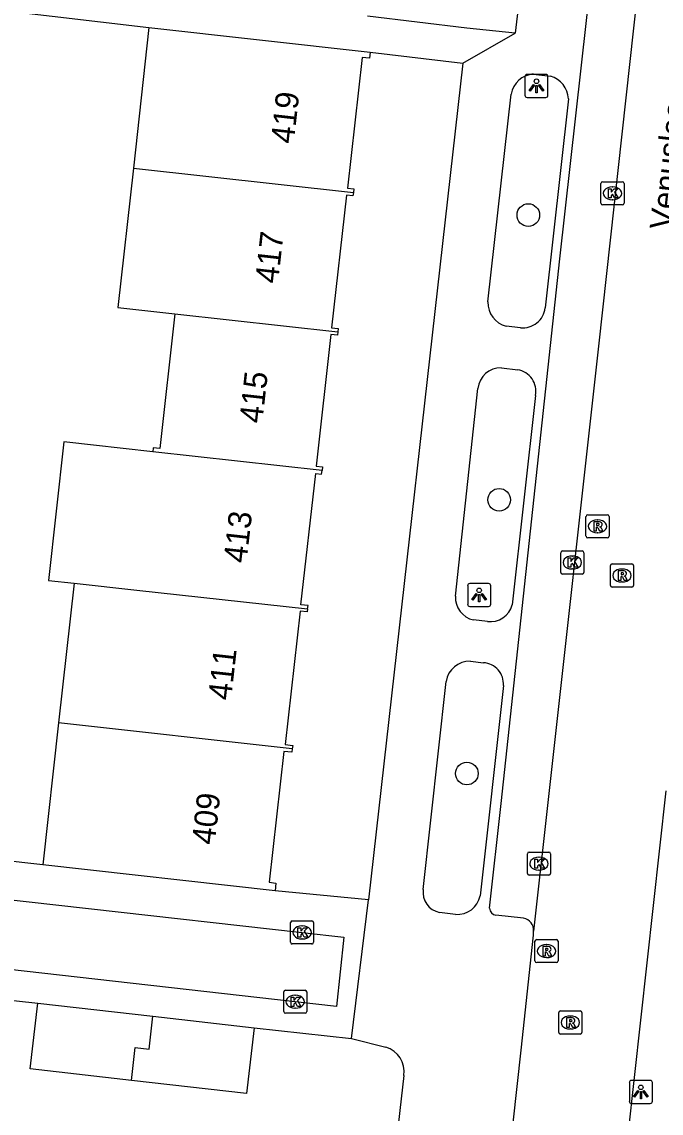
# Model space of a CAD drawing. Extents: x 161928 to 163055, y 386475 to 387428.
# Drawn here: x 162058.37 to 162086.04, y 386860.17 to 386907.42 of the extents above; entities that cross this region are included whole.
import ezdxf

# ---------------------------------------------------------------- set-up
doc = ezdxf.new("R2010")
doc.units = 0
for name, color, linetype in [('IMGEO_Boom', 7, 'Continuous'), ('IMGEO_Kolk', 7, 'Continuous'), ('IMGEO_Lichtpunt', 7, 'Continuous'), ('IMGEO_Openbare_ruimte_label', 7, 'Continuous'), ('IMGEO_Pand', 7, 'Continuous'), ('IMGEO_Pand_nummerreeks', 7, 'Continuous'), ('IMGEO_Rijbaan_lokaal_open', 7, 'Continuous'), ('IMGEO_Rioolput', 7, 'Continuous'), ('IMGEO_Voetpad_open', 7, 'Continuous')]:
    doc.layers.add(name, color=color, linetype=linetype)

msp = doc.modelspace()

# ---------------------------------------------------------------- linework, layer by layer
at = {"layer": 'IMGEO_Boom'}
for centre in [(162080.288, 386899.055), (162079.03, 386886.729), (162077.631, 386874.872)]:
    msp.add_circle(centre, 0.489, dxfattribs=at)
at = {"layer": 'IMGEO_Kolk'}
for p, q in [((162083.43, 386899.569), (162083.43, 386900.421)), ((162083.505, 386900.495), (162084.357, 386900.495)), ((162084.431, 386900.421), (162084.431, 386899.569)), ((162083.918, 386900.275), (162083.943, 386900.275)), ((162084.357, 386899.495), (162083.505, 386899.495)), ((162083.941, 386899.715), (162083.916, 386899.715)), ((162081.691, 386883.585), (162081.691, 386884.437)), ((162081.766, 386884.511), (162082.618, 386884.511)), ((162082.692, 386884.437), (162082.692, 386883.585)), ((162082.179, 386884.291), (162082.204, 386884.291)), ((162082.618, 386883.511), (162081.766, 386883.511)), ((162082.202, 386883.731), (162082.177, 386883.731)), ((162080.248, 386870.548), (162080.248, 386871.4)), ((162080.323, 386871.474), (162081.175, 386871.474)), ((162080.736, 386871.254), (162080.761, 386871.254)), ((162081.249, 386871.4), (162081.249, 386870.548)), ((162080.759, 386870.694), (162080.734, 386870.694)), ((162081.175, 386870.474), (162080.323, 386870.474)), ((162069.996, 386867.568), (162069.996, 386868.42)), ((162070.071, 386868.494), (162070.923, 386868.494)), ((162070.484, 386868.274), (162070.509, 386868.274)), ((162070.997, 386868.42), (162070.997, 386867.568)), ((162070.923, 386867.494), (162070.071, 386867.494)), ((162070.507, 386867.714), (162070.482, 386867.714)), ((162069.7, 386864.569), (162069.7, 386865.421)), ((162069.775, 386865.495), (162070.627, 386865.495)), ((162070.701, 386865.421), (162070.701, 386864.569)), ((162070.188, 386865.275), (162070.213, 386865.275)), ((162070.627, 386864.495), (162069.775, 386864.495)), ((162070.211, 386864.715), (162070.186, 386864.715))]:
    msp.add_line(p, q, dxfattribs=at)
for points in [[(162083.43, 386899.569), (162083.43, 386900.421)], [(162083.505, 386900.495), (162084.357, 386900.495)], [(162084.431, 386900.421), (162084.431, 386899.569)], [(162083.751, 386900.195), (162083.874, 386900.195), (162083.874, 386900.044), (162084.004, 386900.195), (162084.168, 386900.195), (162084.022, 386900.044), (162084.175, 386899.795), (162084.023, 386899.795), (162083.938, 386899.959), (162083.874, 386899.892), (162083.874, 386899.795), (162083.751, 386899.795), (162083.751, 386900.195)], [(162084.357, 386899.495), (162083.505, 386899.495)], [(162081.691, 386883.585), (162081.691, 386884.437)], [(162081.766, 386884.511), (162082.618, 386884.511)], [(162082.692, 386884.437), (162082.692, 386883.585)], [(162082.012, 386884.211), (162082.135, 386884.211), (162082.135, 386884.06), (162082.265, 386884.211), (162082.429, 386884.211), (162082.283, 386884.06), (162082.436, 386883.811), (162082.284, 386883.811), (162082.199, 386883.975), (162082.135, 386883.908), (162082.135, 386883.811), (162082.012, 386883.811), (162082.012, 386884.211)], [(162082.618, 386883.511), (162081.766, 386883.511)], [(162080.248, 386870.548), (162080.248, 386871.4)], [(162080.323, 386871.474), (162081.175, 386871.474)], [(162080.569, 386871.174), (162080.692, 386871.174), (162080.692, 386871.023), (162080.822, 386871.174), (162080.986, 386871.174), (162080.84, 386871.023), (162080.993, 386870.774), (162080.841, 386870.774), (162080.756, 386870.938), (162080.692, 386870.871), (162080.692, 386870.774), (162080.569, 386870.774), (162080.569, 386871.174)], [(162081.249, 386871.4), (162081.249, 386870.548)], [(162081.175, 386870.474), (162080.323, 386870.474)], [(162069.996, 386867.568), (162069.996, 386868.42)], [(162070.071, 386868.494), (162070.923, 386868.494)], [(162070.997, 386868.42), (162070.997, 386867.568)], [(162070.317, 386868.194), (162070.44, 386868.194), (162070.44, 386868.043), (162070.57, 386868.194), (162070.734, 386868.194), (162070.588, 386868.043), (162070.741, 386867.794), (162070.589, 386867.794), (162070.504, 386867.958), (162070.44, 386867.891), (162070.44, 386867.794), (162070.317, 386867.794), (162070.317, 386868.194)], [(162070.923, 386867.494), (162070.071, 386867.494)], [(162069.7, 386864.569), (162069.7, 386865.421)], [(162069.775, 386865.495), (162070.627, 386865.495)], [(162070.701, 386865.421), (162070.701, 386864.569)], [(162070.021, 386865.195), (162070.144, 386865.195), (162070.144, 386865.044), (162070.274, 386865.195), (162070.438, 386865.195), (162070.292, 386865.044), (162070.445, 386864.795), (162070.293, 386864.795), (162070.208, 386864.959), (162070.144, 386864.892), (162070.144, 386864.795), (162070.021, 386864.795), (162070.021, 386865.195)], [(162070.627, 386864.495), (162069.775, 386864.495)]]:
    msp.add_lwpolyline(points, dxfattribs=at)
for centre, start, end in [((162083.507, 386900.419), 91.552, 178.448), ((162083.507, 386900.419), 91.552, 178.448), ((162084.355, 386900.419), 1.552, 88.448), ((162084.355, 386900.419), 1.552, 88.448), ((162083.507, 386899.571), 181.552, 268.448), ((162083.507, 386899.571), 181.552, 268.448), ((162084.355, 386899.571), 271.552, 358.448), ((162084.355, 386899.571), 271.552, 358.448), ((162081.768, 386884.435), 91.552, 178.448), ((162081.768, 386884.435), 91.552, 178.448), ((162082.616, 386884.435), 1.552, 88.448), ((162082.616, 386884.435), 1.552, 88.448), ((162081.768, 386883.587), 181.552, 268.448), ((162081.768, 386883.587), 181.552, 268.448), ((162082.616, 386883.587), 271.552, 358.448), ((162082.616, 386883.587), 271.552, 358.448), ((162080.325, 386871.398), 91.552, 178.448), ((162080.325, 386871.398), 91.552, 178.448), ((162081.173, 386871.398), 1.552, 88.448), ((162081.173, 386871.398), 1.552, 88.448), ((162080.325, 386870.55), 181.552, 268.448), ((162080.325, 386870.55), 181.552, 268.448), ((162081.173, 386870.55), 271.552, 358.448), ((162081.173, 386870.55), 271.552, 358.448), ((162070.073, 386868.418), 91.552, 178.448), ((162070.073, 386868.418), 91.552, 178.448), ((162070.921, 386868.418), 1.552, 88.448), ((162070.921, 386868.418), 1.552, 88.448), ((162070.073, 386867.57), 181.552, 268.448), ((162070.073, 386867.57), 181.552, 268.448), ((162070.921, 386867.57), 271.552, 358.448), ((162070.921, 386867.57), 271.552, 358.448), ((162069.777, 386865.419), 91.552, 178.448), ((162069.777, 386865.419), 91.552, 178.448), ((162070.625, 386865.419), 1.552, 88.448), ((162070.625, 386865.419), 1.552, 88.448), ((162069.777, 386864.571), 181.552, 268.448), ((162069.777, 386864.571), 181.552, 268.448), ((162070.625, 386864.571), 271.552, 358.448), ((162070.625, 386864.571), 271.552, 358.448)]:
    msp.add_arc(centre, 0.0765, start, end, dxfattribs=at)
for centre, major_axis, ratio, start_param, end_param in [((162083.917, 386899.995), (-0.387, 0.002), 0.722429, 4.712389, 7.853982), ((162083.942, 386899.995), (-0.39, 0.002), 0.717154, 1.570796, 4.712389), ((162082.178, 386884.011), (-0.387, 0.002), 0.722429, 4.712389, 7.853982), ((162082.203, 386884.011), (-0.39, 0.002), 0.717154, 1.570796, 4.712389), ((162080.735, 386870.974), (-0.387, 0.002), 0.722429, 4.712389, 7.853982), ((162080.76, 386870.974), (-0.39, 0.002), 0.717154, 1.570796, 4.712389), ((162070.483, 386867.994), (-0.387, 0.002), 0.722429, 4.712389, 7.853982), ((162070.508, 386867.994), (-0.39, 0.002), 0.717154, 1.570796, 4.712389), ((162070.187, 386864.995), (-0.387, 0.002), 0.722429, 4.712389, 7.853982), ((162070.212, 386864.995), (-0.39, 0.002), 0.717154, 1.570796, 4.712389)]:
    msp.add_ellipse(centre, major_axis=major_axis, ratio=ratio, start_param=start_param, end_param=end_param, dxfattribs=at)
at = {"layer": 'IMGEO_Lichtpunt'}
for p, q in [((162081.045, 386905.144), (162080.237, 386905.144)), ((162081.045, 386905.144), (162080.237, 386905.144)), ((162080.143, 386905.049), (162080.143, 386904.242)), ((162080.143, 386905.049), (162080.143, 386904.242)), ((162081.139, 386904.242), (162081.139, 386905.049)), ((162081.139, 386904.242), (162081.139, 386905.049)), ((162080.237, 386904.148), (162081.045, 386904.148)), ((162080.237, 386904.148), (162081.045, 386904.148)), ((162077.663, 386883.008), (162077.663, 386882.201)), ((162077.663, 386883.008), (162077.663, 386882.201)), ((162078.565, 386883.103), (162077.757, 386883.103)), ((162078.565, 386883.103), (162077.757, 386883.103)), ((162078.659, 386882.201), (162078.659, 386883.008)), ((162078.659, 386882.201), (162078.659, 386883.008)), ((162077.757, 386882.107), (162078.565, 386882.107)), ((162077.757, 386882.107), (162078.565, 386882.107)), ((162084.66, 386861.491), (162084.66, 386860.684)), ((162084.66, 386861.491), (162084.66, 386860.684)), ((162085.562, 386861.586), (162084.754, 386861.586)), ((162085.562, 386861.586), (162084.754, 386861.586)), ((162085.656, 386860.684), (162085.656, 386861.491)), ((162085.656, 386860.684), (162085.656, 386861.491)), ((162084.754, 386860.59), (162085.562, 386860.59)), ((162084.754, 386860.59), (162085.562, 386860.59))]:
    msp.add_line(p, q, dxfattribs=at)
for points in [[(162080.517, 386904.713), (162080.556, 386904.685), (162080.368, 386904.423), (162080.33, 386904.45), (162080.517, 386904.713)], [(162080.619, 386904.665), (162080.666, 386904.665), (162080.666, 386904.343), (162080.619, 386904.343), (162080.619, 386904.665)], [(162080.729, 386904.685), (162080.767, 386904.712), (162080.954, 386904.45), (162080.915, 386904.422), (162080.729, 386904.685)], [(162078.037, 386882.672), (162078.076, 386882.644), (162077.888, 386882.382), (162077.85, 386882.409), (162078.037, 386882.672)], [(162078.139, 386882.624), (162078.186, 386882.624), (162078.186, 386882.302), (162078.139, 386882.302), (162078.139, 386882.624)], [(162078.249, 386882.644), (162078.287, 386882.671), (162078.474, 386882.409), (162078.435, 386882.381), (162078.249, 386882.644)], [(162085.034, 386861.155), (162085.073, 386861.127), (162084.885, 386860.865), (162084.847, 386860.892), (162085.034, 386861.155)], [(162085.246, 386861.127), (162085.284, 386861.154), (162085.471, 386860.892), (162085.432, 386860.864), (162085.246, 386861.127)], [(162085.136, 386861.107), (162085.183, 386861.107), (162085.183, 386860.785), (162085.136, 386860.785), (162085.136, 386861.107)]]:
    msp.add_lwpolyline(points, dxfattribs=at)
for centre in [(162080.642, 386904.847), (162078.162, 386882.806), (162085.159, 386861.289)]:
    msp.add_circle(centre, 0.0994, dxfattribs=at)
for centre, start, end in [((162080.237, 386905.049), 90, 180), ((162080.237, 386905.049), 90, 180), ((162081.045, 386905.049), 0, 90), ((162081.045, 386905.049), 0, 90), ((162080.237, 386904.242), 180, 270), ((162080.237, 386904.242), 180, 270), ((162081.045, 386904.242), 270, 0), ((162081.045, 386904.242), 270, 360), ((162077.757, 386883.008), 90, 180), ((162077.757, 386883.008), 90, 180), ((162078.565, 386883.008), 0, 90), ((162078.565, 386883.008), 0, 90), ((162077.757, 386882.201), 180, 270), ((162077.757, 386882.201), 180, 270), ((162078.565, 386882.201), 270, 0), ((162078.565, 386882.201), 270, 360), ((162084.754, 386861.491), 90, 180), ((162084.754, 386861.491), 90, 180), ((162085.562, 386861.491), 0, 90), ((162085.562, 386861.491), 0, 90), ((162084.754, 386860.684), 180, 270), ((162084.754, 386860.684), 180, 270), ((162085.562, 386860.684), 270, 0), ((162085.562, 386860.684), 270, 360)]:
    msp.add_arc(centre, 0.0946, start, end, dxfattribs=at)
at = {"layer": 'IMGEO_Pand'}
for points in [[(162063.867, 386907.179), (162063.194, 386901.092)], [(162063.867, 386907.179), (162073.446, 386906.104)], [(162073.446, 386906.104), (162073.417, 386905.844), (162073.091, 386905.88), (162072.457, 386900.224), (162072.734, 386900.193), (162072.717, 386900.038)], [(162063.194, 386901.092), (162062.525, 386895.048), (162064.995, 386894.775)], [(162063.194, 386901.092), (162072.717, 386900.038)], [(162072.717, 386900.038), (162072.699, 386899.881), (162072.416, 386899.913), (162071.773, 386894.172), (162072.057, 386894.14), (162072.041, 386893.995)], [(162064.995, 386894.775), (162064.341, 386888.944), (162064.055, 386888.976), (162064.036, 386888.809)], [(162064.995, 386894.775), (162072.041, 386893.995)], [(162072.041, 386893.995), (162072.024, 386893.848), (162071.746, 386893.879), (162071.107, 386888.184), (162071.376, 386888.154), (162071.359, 386887.998)], [(162064.036, 386888.809), (162060.19, 386889.235), (162059.525, 386883.232), (162060.631, 386883.11)], [(162071.359, 386887.998), (162064.036, 386888.809)], [(162070.738, 386882.008), (162070.753, 386882.146), (162070.449, 386882.18), (162071.087, 386887.87), (162071.341, 386887.841), (162071.359, 386887.998)], [(162060.631, 386883.11), (162059.96, 386877.064)], [(162060.631, 386883.11), (162063.351, 386882.812), (162070.738, 386882.008)], [(162070.738, 386882.008), (162070.722, 386881.87), (162070.418, 386881.904), (162069.77, 386876.13), (162070.09, 386876.094), (162070.073, 386875.945)], [(162059.96, 386877.064), (162059.278, 386870.918)], [(162070.073, 386875.945), (162059.96, 386877.064)], [(162070.073, 386875.945), (162070.056, 386875.796), (162069.707, 386875.835), (162069.071, 386870.166), (162069.363, 386870.134), (162069.325, 386869.792)], [(162069.325, 386869.792), (162059.278, 386870.918)], [(162063.113, 386861.587), (162058.73, 386862.086), (162059.054, 386864.932)], [(162059.054, 386864.932), (162064.034, 386864.365)], [(162063.113, 386861.587), (162063.275, 386863.01), (162063.872, 386862.942), (162064.034, 386864.365)], [(162064.034, 386864.365), (162068.418, 386863.866)], [(162068.418, 386863.866), (162068.094, 386861.02), (162063.113, 386861.587)]]:
    msp.add_lwpolyline(points, dxfattribs=at)
at = {"layer": 'IMGEO_Rijbaan_lokaal_open'}
for points in [[(162087.202, 386928.662), (162083.328, 386893.374), (162081.119, 386873.495), (162080.519, 386868.055)], [(162084.603, 386859.23), (162086.247, 386874.125)], [(162050.693, 386870.214), (162051.991, 386870.069), (162070.497, 386867.994), (162072.306, 386867.789), (162071.98, 386864.795), (162070.201, 386864.995), (162051.445, 386867.107), (162040.29, 386868.47)], [(162079.639, 386859.749), (162079.983, 386862.893), (162080.511, 386867.872), (162080.519, 386868.055)]]:
    msp.add_lwpolyline(points, dxfattribs=at)
at = {"layer": 'IMGEO_Rioolput'}
for p, q in [((162082.784, 386885.151), (162082.784, 386886.003)), ((162082.859, 386886.077), (162083.711, 386886.077)), ((162083.272, 386885.857), (162083.297, 386885.857)), ((162083.785, 386886.003), (162083.785, 386885.151)), ((162083.295, 386885.297), (162083.27, 386885.297)), ((162083.711, 386885.077), (162082.859, 386885.077)), ((162083.842, 386883.023), (162083.842, 386883.875)), ((162083.917, 386883.949), (162084.769, 386883.949)), ((162084.843, 386883.875), (162084.843, 386883.023)), ((162084.33, 386883.729), (162084.355, 386883.729)), ((162084.769, 386882.949), (162083.917, 386882.949)), ((162084.353, 386883.169), (162084.328, 386883.169)), ((162080.575, 386866.761), (162080.575, 386867.613)), ((162080.65, 386867.687), (162081.502, 386867.687)), ((162081.063, 386867.467), (162081.088, 386867.467)), ((162081.576, 386867.613), (162081.576, 386866.761)), ((162081.086, 386866.907), (162081.061, 386866.907)), ((162081.502, 386866.687), (162080.65, 386866.687)), ((162081.606, 386863.669), (162081.606, 386864.521)), ((162081.681, 386864.595), (162082.533, 386864.595)), ((162082.607, 386864.521), (162082.607, 386863.669)), ((162082.094, 386864.375), (162082.119, 386864.375)), ((162082.533, 386863.595), (162081.681, 386863.595)), ((162082.117, 386863.815), (162082.092, 386863.815))]:
    msp.add_line(p, q, dxfattribs=at)
for points in [[(162082.784, 386885.151), (162082.784, 386886.003)], [(162082.859, 386886.077), (162083.711, 386886.077)], [(162083.373, 386885.775), (162083.121, 386885.777), (162083.121, 386885.377)], [(162083.785, 386886.003), (162083.785, 386885.151)], [(162083.121, 386885.377), (162083.245, 386885.377), (162083.245, 386885.539), (162083.256, 386885.539)], [(162083.299, 386885.696), (162083.245, 386885.696), (162083.245, 386885.615)], [(162083.245, 386885.615), (162083.297, 386885.615)], [(162083.303, 386885.51), (162083.374, 386885.377), (162083.514, 386885.377), (162083.449, 386885.503)], [(162083.711, 386885.077), (162082.859, 386885.077)], [(162083.842, 386883.023), (162083.842, 386883.875)], [(162083.917, 386883.949), (162084.769, 386883.949)], [(162084.843, 386883.875), (162084.843, 386883.023)], [(162084.431, 386883.647), (162084.179, 386883.649), (162084.179, 386883.249)], [(162084.179, 386883.249), (162084.303, 386883.249), (162084.303, 386883.411), (162084.314, 386883.411)], [(162084.357, 386883.568), (162084.303, 386883.568), (162084.303, 386883.487)], [(162084.303, 386883.487), (162084.355, 386883.487)], [(162084.361, 386883.382), (162084.432, 386883.249), (162084.572, 386883.249), (162084.507, 386883.375)], [(162084.769, 386882.949), (162083.917, 386882.949)], [(162080.575, 386866.761), (162080.575, 386867.613)], [(162080.65, 386867.687), (162081.502, 386867.687)], [(162081.164, 386867.385), (162080.912, 386867.387), (162080.912, 386866.987)], [(162081.09, 386867.306), (162081.036, 386867.306), (162081.036, 386867.225)], [(162081.576, 386867.613), (162081.576, 386866.761)], [(162080.912, 386866.987), (162081.036, 386866.987), (162081.036, 386867.149), (162081.047, 386867.149)], [(162081.036, 386867.225), (162081.088, 386867.225)], [(162081.094, 386867.12), (162081.165, 386866.987), (162081.305, 386866.987), (162081.24, 386867.113)], [(162081.502, 386866.687), (162080.65, 386866.687)], [(162081.606, 386863.669), (162081.606, 386864.521)], [(162081.681, 386864.595), (162082.533, 386864.595)], [(162082.607, 386864.521), (162082.607, 386863.669)], [(162082.195, 386864.293), (162081.943, 386864.295), (162081.943, 386863.895)], [(162081.943, 386863.895), (162082.067, 386863.895), (162082.067, 386864.057), (162082.078, 386864.057)], [(162082.121, 386864.214), (162082.067, 386864.214), (162082.067, 386864.133)], [(162082.067, 386864.133), (162082.119, 386864.133)], [(162082.125, 386864.028), (162082.196, 386863.895), (162082.336, 386863.895), (162082.271, 386864.021)], [(162082.533, 386863.595), (162081.681, 386863.595)]]:
    msp.add_lwpolyline(points, dxfattribs=at)
for centre, radius, start, end in [((162082.861, 386886.001), 0.0765, 91.552, 178.448), ((162082.861, 386886.001), 0.0765, 91.552, 178.448), ((162083.372, 386885.665), 0.109, 350.3612, 89.416), ((162083.709, 386886.001), 0.0765, 1.552, 88.448), ((162083.709, 386886.001), 0.0765, 1.552, 88.448), ((162083.255, 386885.486), 0.0533, 26.0293, 88.6989), ((162083.281, 386885.804), 0.19, 274.7715, 282.9687), ((162083.305, 386885.6), 0.0964, 77.0061, 93.1865), ((162083.319, 386885.657), 0.0378, 276.6634, 79.6772), ((162083.37, 386885.665), 0.112, 277.5842, 350.9817), ((162083.354, 386885.45), 0.108, 29.5134, 73.7905), ((162082.861, 386885.153), 0.0765, 181.552, 268.448), ((162082.861, 386885.153), 0.0765, 181.552, 268.448), ((162083.709, 386885.153), 0.0765, 271.552, 358.448), ((162083.709, 386885.153), 0.0765, 271.552, 358.448), ((162083.919, 386883.873), 0.0765, 91.552, 178.448), ((162083.919, 386883.873), 0.0765, 91.552, 178.448), ((162084.767, 386883.873), 0.0765, 1.552, 88.448), ((162084.767, 386883.873), 0.0765, 1.552, 88.448), ((162084.313, 386883.358), 0.0533, 26.0293, 88.6989), ((162084.339, 386883.676), 0.19, 274.7715, 282.9687), ((162084.363, 386883.472), 0.0964, 77.0061, 93.1865), ((162084.377, 386883.529), 0.0378, 276.6634, 79.6772), ((162084.43, 386883.537), 0.109, 350.3612, 89.416), ((162084.428, 386883.537), 0.112, 277.5842, 350.9817), ((162084.412, 386883.322), 0.108, 29.5134, 73.7905), ((162083.919, 386883.025), 0.0765, 181.552, 268.448), ((162083.919, 386883.025), 0.0765, 181.552, 268.448), ((162084.767, 386883.025), 0.0765, 271.552, 358.448), ((162084.767, 386883.025), 0.0765, 271.552, 358.448), ((162080.652, 386867.611), 0.0765, 91.552, 178.448), ((162080.652, 386867.611), 0.0765, 91.552, 178.448), ((162081.096, 386867.21), 0.0964, 77.0061, 93.1865), ((162081.11, 386867.267), 0.0378, 276.6634, 79.6772), ((162081.163, 386867.275), 0.109, 350.3612, 89.416), ((162081.5, 386867.611), 0.0765, 1.552, 88.448), ((162081.5, 386867.611), 0.0765, 1.552, 88.448), ((162081.046, 386867.096), 0.0533, 26.0293, 88.6989), ((162081.072, 386867.414), 0.19, 274.7715, 282.9687), ((162081.161, 386867.275), 0.112, 277.5842, 350.9817), ((162081.145, 386867.06), 0.108, 29.5134, 73.7905), ((162080.652, 386866.763), 0.0765, 181.552, 268.448), ((162080.652, 386866.763), 0.0765, 181.552, 268.448), ((162081.5, 386866.763), 0.0765, 271.552, 358.448), ((162081.5, 386866.763), 0.0765, 271.552, 358.448), ((162081.683, 386864.519), 0.0765, 91.552, 178.448), ((162081.683, 386864.519), 0.0765, 91.552, 178.448), ((162082.531, 386864.519), 0.0765, 1.552, 88.448), ((162082.531, 386864.519), 0.0765, 1.552, 88.448), ((162082.077, 386864.004), 0.0533, 26.0293, 88.6989), ((162082.103, 386864.322), 0.19, 274.7715, 282.9687), ((162082.127, 386864.118), 0.0964, 77.0061, 93.1865), ((162082.141, 386864.175), 0.0378, 276.6634, 79.6772), ((162082.194, 386864.183), 0.109, 350.3612, 89.416), ((162082.192, 386864.183), 0.112, 277.5842, 350.9817), ((162082.176, 386863.968), 0.108, 29.5134, 73.7905), ((162081.683, 386863.671), 0.0765, 181.552, 268.448), ((162081.683, 386863.671), 0.0765, 181.552, 268.448), ((162082.531, 386863.671), 0.0765, 271.552, 358.448), ((162082.531, 386863.671), 0.0765, 271.552, 358.448)]:
    msp.add_arc(centre, radius, start, end, dxfattribs=at)
for centre, major_axis, ratio, start_param, end_param in [((162083.271, 386885.577), (-0.387, 0.002), 0.722429, 4.712389, 7.853982), ((162083.296, 386885.577), (-0.39, 0.002), 0.717154, 1.570796, 4.712389), ((162084.329, 386883.449), (-0.387, 0.002), 0.722429, 4.712389, 7.853982), ((162084.354, 386883.449), (-0.39, 0.002), 0.717154, 1.570796, 4.712389), ((162081.062, 386867.187), (-0.387, 0.002), 0.722429, 4.712389, 7.853982), ((162081.087, 386867.187), (-0.39, 0.002), 0.717154, 1.570796, 4.712389), ((162082.093, 386864.095), (-0.387, 0.002), 0.722429, 4.712389, 7.853982), ((162082.118, 386864.095), (-0.39, 0.002), 0.717154, 1.570796, 4.712389)]:
    msp.add_ellipse(centre, major_axis=major_axis, ratio=ratio, start_param=start_param, end_param=end_param, dxfattribs=at)
at = {"layer": 'IMGEO_Voetpad_open'}
for points in [[(162082.324, 386929.045), (162079.716, 386906.933)], [(162078.608, 386869.048), (162079.116, 386873.581), (162081.656, 386897.155), (162085.114, 386928.126)], [(162053.496, 386906.858), (162053.642, 386908.384), (162063.867, 386907.179)], [(162079.716, 386906.933), (162077.624, 386907.142), (162073.326, 386907.663)], [(162077.454, 386905.628), (162079.716, 386906.933)], [(162073.446, 386906.104), (162077.454, 386905.628)], [(162077.454, 386905.628), (162073.376, 386869.412)], [(162080.493, 386905.162), (162081.254, 386905.07)], [(162078.538, 386895.291), (162079.548, 386904.291)], [(162082.02, 386904.091), (162081.016, 386895.032)], [(162079.954, 386894.179), (162079.33, 386894.251)], [(162079.122, 386892.436), (162079.829, 386892.36)], [(162077.131, 386882.55), (162078.11, 386891.543)], [(162080.594, 386891.246), (162079.589, 386882.183)], [(162078.515, 386881.457), (162077.91, 386881.523)], [(162077.782, 386879.739), (162078.348, 386879.671)], [(162075.739, 386869.86), (162076.726, 386878.86)], [(162079.21, 386878.687), (162078.2, 386869.58)], [(162059.278, 386870.918), (162049.592, 386872.006), (162049.724, 386873.301)], [(162073.376, 386869.412), (162069.325, 386869.792)], [(162072.637, 386863.4), (162073.376, 386869.412)], [(162077.139, 386868.777), (162076.446, 386868.857)], [(162080.085, 386868.612), (162078.887, 386868.739)], [(162056.402, 386865.226), (162059.054, 386864.932)], [(162068.418, 386863.866), (162072.637, 386863.4)], [(162072.637, 386863.4), (162074.116, 386863.024)], [(162074.895, 386861.796), (162072.375, 386839.683)]]:
    msp.add_lwpolyline(points, dxfattribs=at)
for centre, radius, start, end in [((162080.582, 386904.118), 1.048, 94.8588, 170.4743), ((162080.931, 386904.028), 1.091, 3.3147, 72.7668), ((162079.571, 386895.256), 1.034, 178.0841, 256.4972), ((162080.06, 386895.134), 0.961, 263.6545, 353.8885), ((162079.089, 386891.454), 0.983, 88.0481, 174.803), ((162079.676, 386891.435), 0.937, 348.3427, 80.6132), ((162078.143, 386882.509), 1.013, 177.6674, 256.6947), ((162078.638, 386882.433), 0.984, 262.8429, 345.2727), ((162077.756, 386878.696), 1.043, 88.5932, 170.9539), ((162078.301, 386878.76), 0.912, 355.3867, 87.0511), ((162076.633, 386869.739), 0.902, 172.2988, 258.0601), ((162077.217, 386869.777), 1.003, 265.561, 348.6783), ((162078.934, 386869.062), 0.326, 182.3974, 261.7611), ((162079.988, 386868.089), 0.532, 356.3846, 79.465), ((162073.828, 386861.98), 1.083, 350.2201, 74.5592)]:
    msp.add_arc(centre, radius, start, end, dxfattribs=at)

# ---------------------------------------------------------------- texts
at = {"layer": 'IMGEO_Openbare_ruimte_label'}
msp.add_text('Venuslaan', height=1, rotation=83.7421, dxfattribs=at).set_placement((162086.53, 386898.387))
at = {"layer": 'IMGEO_Pand_nummerreeks'}
for s, rotation, p in [('419', 83.5778, (162070.131, 386902.117)), ('417', 83.5774, (162069.451, 386896.064)), ('415', 83.5774, (162068.769, 386890.011)), ('413', 83.5774, (162068.088, 386883.959)), ('411', 83.5778, (162067.419, 386878.019)), ('409', 83.5778, (162066.714, 386871.762))]:
    msp.add_text(s, height=1, rotation=rotation, dxfattribs=at).set_placement(p)

doc.saveas('drawing.dxf')
